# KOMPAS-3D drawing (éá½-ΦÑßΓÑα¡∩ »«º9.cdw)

Views: Вид 1, Вид 2
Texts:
  Вал-шестерня
  Noncommercial version
  Заголовки
  Normal
  Ra2.5
  Ra3.2
  Ra1,6
  R 0,3 max
  Ra0.8
  Модуль
  Число зубьев
  Угол наклона
  Symbol type B
  Symbol type A
  Направление линии зуба
  правое
  Нормальный исходный контур
  ГОСТ 13755-81
  Коэффициент смещения
  Средняя длина общей нормали
  Делительный диаметр
  Высота зуба
  Обозначение чертежа сопряженного зубчатого колеса
  ТВЧ h 0,8...1,2; 48...52 HRC Э
  Ra6.3
  1. Улучшение; 235...262 HВ.
  2.  H14, h14,    IT14 2 .
  3. * Размер обеспечить инструментом.
  Сталь 40Х ГОСТ 4543-71
  ДГТУ
Dimensions and other numbers on the sheet: 234; 26,8; 45; 25; 82; 8; 70; 53; 77,53; 1,6; 47,5; 48; 73; 410; 3 фаски; 1; 6; 12; 35; 40; 0,02; 0,004; 0,025; 3,5; 20; 0; 26,833 -0,060 -0,160; 70,53; 7,88; 000.09; 0,05; 0,04; 0,086; 3; 0,3; 0,5; 1:1; 0,6; 2; 4; 5; 7; 9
